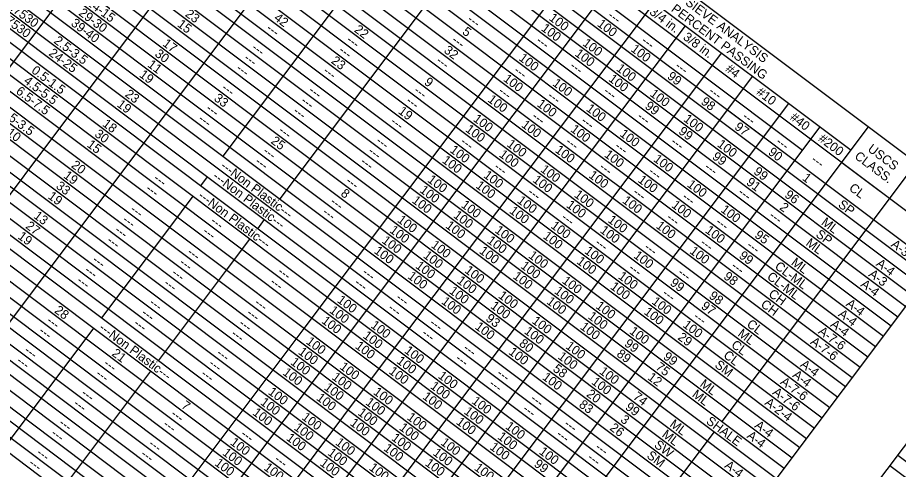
# Model space of a CAD drawing. Extents: x 627484.2 to 627517.5, y 367968.7 to 367996.9.
# Drawn here: x 627486.93 to 627492.24, y 367991.4 to 367994.12 of the extents above; entities that cross this region are included whole.
import ezdxf

# ---------------------------------------------------------------- set-up
doc = ezdxf.new("R2010")
doc.units = 0
doc.layers.add('Default', color=7, linetype='Continuous')

msp = doc.modelspace()

# ---------------------------------------------------------------- linework, layer by layer
at = {"layer": 'Default'}
for p, q in [((627487.4769, 367996.9012), (627492.7198, 367992.9642)), ((627487.3159, 367996.6868), (627492.5588, 367992.7498)), ((627487.2661, 367996.6205), (627491.6592, 367993.3217)), ((627487.2193, 367996.5581), (627491.4252, 367993.3998)), ((627487.1724, 367996.4958), (627492.4153, 367992.5588)), ((627487.1314, 367996.4412), (627492.3744, 367992.5042)), ((627487.0846, 367996.3788), (627492.3275, 367992.4419)), ((627487.0378, 367996.3164), (627492.2807, 367992.3795)), ((627486.9909, 367996.2541), (627492.2338, 367992.3171)), ((627486.95, 367996.1995), (627492.1929, 367992.2625)), ((627486.9031, 367996.1371), (627492.146, 367992.2002)), ((627486.7668, 367993.6668), (627488.5759, 367996.0759)), ((627486.8563, 367996.0747), (627492.0992, 367992.1378)), ((627486.8094, 367996.0124), (627492.0524, 367992.0754)), ((627486.7626, 367995.95), (627492.0055, 367992.013)), ((627486.7158, 367995.8876), (627491.9587, 367991.9507)), ((627486.6748, 367995.833), (627491.9177, 367991.8961)), ((627486.628, 367995.7707), (627491.8709, 367991.8337)), ((627487.1372, 367993.3887), (627488.9462, 367995.7978)), ((627486.5811, 367995.7083), (627491.824, 367991.7713)), ((627486.5343, 367995.6459), (627491.7772, 367991.709)), ((627486.4874, 367995.5836), (627491.7304, 367991.6466)), ((627486.4406, 367995.5212), (627491.6835, 367991.5842)), ((627487.5036, 367993.1135), (627489.3127, 367995.5227)), ((627486.3996, 367995.4666), (627491.6425, 367991.5297)), ((627486.3528, 367995.4042), (627491.5957, 367991.4673)), ((627486.306, 367995.3419), (627491.5489, 367991.4049)), ((627486.2591, 367995.2795), (627491.502, 367991.3425)), ((627486.2181, 367995.2249), (627491.461, 367991.288)), ((627486.1713, 367995.1625), (627491.4142, 367991.2256)), ((627486.1245, 367995.1002), (627491.3674, 367991.1632)), ((627486.0776, 367995.0378), (627491.3205, 367991.1008)), ((627486.0308, 367994.9754), (627491.2737, 367991.0385)), ((627485.9898, 367994.9208), (627491.2327, 367990.9839)), ((627485.943, 367994.8585), (627491.1859, 367990.9215)), ((627485.8961, 367994.7961), (627491.139, 367990.8591)), ((627485.8552, 367994.7415), (627491.0981, 367990.8046)), ((627485.8083, 367994.6791), (627491.0512, 367990.7422)), ((627488.6575, 367992.247), (627490.4666, 367994.6562)), ((627485.7615, 367994.6168), (627491.0044, 367990.6798)), ((627488.1687, 367993.2847), (627489.1698, 367994.6179)), ((627485.7146, 367994.5544), (627490.9576, 367990.6175)), ((627490.3612, 367994.5159), (627491.9517, 367993.3215)), ((627485.6678, 367994.492), (627490.9107, 367990.5551)), ((627485.621, 367994.4297), (627490.8639, 367990.4927)), ((627485.5741, 367994.3673), (627490.817, 367990.4303)), ((627488.5117, 367993.0271), (627489.5128, 367994.3603)), ((627488.8446, 367992.1065), (627490.5483, 367994.3753)), ((627485.5273, 367994.3049), (627490.7702, 367990.368)), ((627485.4805, 367994.2425), (627490.7234, 367990.3056)), ((627485.4395, 367994.188), (627490.6824, 367990.251)), ((627489.0629, 367991.9426), (627490.7666, 367994.2114)), ((627485.3926, 367994.1256), (627490.6356, 367990.1886)), ((627485.3458, 367994.0632), (627490.5887, 367990.1263)), ((627489.25, 367991.8021), (627490.9537, 367994.0709)), ((627485.299, 367994.0008), (627490.5419, 367990.0639)), ((627485.258, 367993.9463), (627490.5009, 367990.0093)), ((627485.2112, 367993.8839), (627490.4541, 367989.9469)), ((627489.4683, 367991.6382), (627491.172, 367993.907)), ((627485.1643, 367993.8215), (627490.4072, 367989.8846)), ((627485.1175, 367993.7592), (627490.3604, 367989.8222)), ((627489.6555, 367991.4977), (627491.3591, 367993.7665)), ((627485.0706, 367993.6968), (627490.3136, 367989.7598)), ((627485.0297, 367993.6422), (627490.2726, 367989.7053)), ((627489.8738, 367991.3337), (627491.5774, 367993.6025)), ((627484.9828, 367993.5798), (627490.2257, 367989.6429)), ((627491.2069, 367993.5638), (627492.4622, 367992.6212)), ((627484.936, 367993.5175), (627490.1789, 367989.5805)), ((627484.895, 367993.4629), (627490.1379, 367989.5259)), ((627490.0609, 367991.1932), (627491.7646, 367993.462)), ((627490.248, 367991.0527), (627492.0571, 367993.4619)), ((627484.8482, 367993.4005), (627490.0911, 367989.4636)), ((627485.6443, 367991.4005), (627487.1372, 367993.3887)), ((627484.8013, 367993.3381), (627490.0442, 367989.4012)), ((627484.7604, 367993.2836), (627490.0033, 367989.3466)), ((627491.1746, 367991.6859), (627492.3455, 367993.2452)), ((627491.8961, 367993.2475), (627492.5588, 367992.7498)), ((627484.7135, 367993.2212), (627489.9564, 367989.2842)), ((627484.6667, 367993.1588), (627489.9096, 367989.2219)), ((627488.034, 367993.1054), (627488.075, 367993.16)), ((627486.0107, 367991.1254), (627487.5036, 367993.1135)), ((627487.8467, 367992.8559), (627487.9872, 367993.043)), ((627490.9576, 367990.6175), (627492.7198, 367992.9642)), ((627487.4368, 367992.3102), (627487.8467, 367992.8559)), ((627488.3771, 367992.8478), (627488.418, 367992.9024)), ((627488.1897, 367992.5983), (627488.3302, 367992.7854)), ((627491.2374, 367990.1574), (627493.1196, 367992.664)), ((627487.7799, 367992.0526), (627488.1897, 367992.5983)), ((627486.3537, 367990.8678), (627487.39, 367992.2478)), ((627487.1646, 367990.2589), (627488.6575, 367992.247)), ((627487.3517, 367990.1184), (627488.8446, 367992.1065)), ((627486.6968, 367990.6102), (627487.7331, 367991.9902)), ((627487.57, 367989.9545), (627489.0629, 367991.9426)), ((627487.7571, 367989.814), (627489.25, 367991.8021)), ((627487.9754, 367989.65), (627489.4683, 367991.6382)), ((627490.5365, 367990.8361), (627491.1278, 367991.6236)), ((627488.1626, 367989.5095), (627489.6555, 367991.4977)), ((627492.2326, 367991.4828), (627497.4755, 367987.5459)), ((627492.1858, 367991.4204), (627497.4287, 367987.4835))]:
    msp.add_line(p, q, dxfattribs=at)

# ---------------------------------------------------------------- texts
for s, p in [('632315.7530', (627486.6876, 367994.3137)), ('632315.7530', (627486.6407, 367994.2514)), ('14-15', (627487.3419, 367994.2004)), ('SIEVE ANALYSIS', (627490.9485, 367994.2018)), ('3/4 in.', (627490.7323, 367994.1449)), ('PERCENT PASSING', (627490.8637, 367994.1623)), ('29-30', (627487.2941, 367994.1387)), ('23', (627487.9356, 367994.1325)), ('42', (627488.4705, 367994.1088)), ('100', (627490.1272, 367994.1085)), ('---', (627490.481, 367994.1233)), ('39-40', (627487.2472, 367994.0764)), ('15', (627487.8882, 367994.0705)), ('22', (627488.9541, 367994.0383)), ('---', (627489.6346, 367994.1004)), ('100', (627490.0803, 367994.0461)), ('100', (627490.4177, 367994.0732)), ('---', (627488.4237, 367994.0465)), ('5', (627489.6049, 367994.0252)), ('3/8 in.', (627490.935, 367993.9927)), ('2.5-3.5', (627487.1442, 367993.9709)), ('17', (627487.7997, 367993.9541)), ('---', (627488.9072, 367993.976)), ('---', (627489.541, 367993.9756)), ('---', (627490.0499, 367993.9714)), ('100', (627490.3299, 367993.9563)), ('---', (627490.6837, 367993.9711)), ('24-25', (627487.1136, 367993.8963)), ('30', (627487.7526, 367993.892)), ('---', (627488.3358, 367993.9295)), ('---', (627488.8604, 367993.9136)), ('32', (627489.4942, 367993.9132)), ('100', (627490.2831, 367993.8939)), ('100', (627490.6204, 367993.921)), ('11', (627487.7086, 367993.8275)), ('---', (627488.289, 367993.8671)), ('23', (627488.8149, 367993.8502)), ('---', (627489.4473, 367993.8509)), ('100', (627489.9457, 367993.8668)), ('0.5-1.5', (627487.0095, 367993.7915)), ('---', (627488.2422, 367993.8048)), ('---', (627488.7667, 367993.7889)), ('---', (627489.9153, 367993.7921)), ('---', (627490.2526, 367993.8192)), ('100', (627490.5326, 367993.8041)), ('---', (627490.8864, 367993.8188)), ('#4', (627491.19, 367993.8011)), ('4.5-5.5', (627486.9627, 367993.7292)), ('19', (627487.6592, 367993.767)), ('9', (627489.3758, 367993.7217)), ('100', (627489.852, 367993.742)), ('100', (627490.4858, 367993.7417)), ('99', (627490.8396, 367993.7564)), ('6.5-7.5', (627486.9158, 367993.6668)), ('---', (627488.1544, 367993.6878)), ('100', (627490.1484, 367993.7146)), ('23', (627487.5727, 367993.6491)), ('33', (627488.1089, 367993.6244)), ('---', (627488.6789, 367993.6719)), ('---', (627489.3126, 367993.6716)), ('100', (627489.7583, 367993.6173)), ('---', (627489.8216, 367993.6674)), ('---', (627490.118, 367993.6399)), ('---', (627490.4553, 367993.667)), ('100', (627490.7353, 367993.6518)), ('---', (627491.0891, 367993.6666)), ('#10', (627491.3763, 367993.6612)), ('19', (627487.5245, 367993.5877)), ('---', (627488.6321, 367993.6095)), ('---', (627489.2658, 367993.6092)), ('100', (627490.0547, 367993.5898)), ('100', (627490.3511, 367993.5624)), ('99', (627490.705, 367993.5771)), ('98', (627491.0428, 367993.6038)), ('2.5-3.5', (627486.8222, 367993.542)), ('---', (627488.0607, 367993.5631)), ('---', (627488.5852, 367993.5472)), ('19', (627489.219, 367993.5468)), ('#40', (627491.5791, 367993.509)), ('9-10', (627486.8068, 367993.456)), ('18', (627487.4372, 367993.4704)), ('---', (627488.0138, 367993.5007)), ('---', (627489.1721, 367993.4844)), ('100', (627489.6705, 367993.5004)), ('100', (627489.9611, 367993.4651)), ('---', (627490.0243, 367993.5151)), ('---', (627490.3207, 367993.4877)), ('---', (627490.658, 367993.5148)), ('100', (627490.938, 367993.4996)), ('97', (627491.2451, 367993.4519)), ('---', (627491.2918, 367993.5144)), ('30', (627487.3896, 367993.4086)), ('---', (627488.4974, 367993.4302)), ('100', (627489.6237, 367993.438)), ('100', (627490.2574, 367993.4376)), ('100', (627490.5538, 367993.4101)), ('99', (627490.9077, 367993.4249)), ('25', (627488.4514, 367993.3672)), ('---', (627489.0843, 367993.3675)), ('#200', (627491.7499, 367993.3807)), ('15', (627487.3438, 367993.3455)), ('100', (627489.53, 367993.3132)), ('---', (627489.5933, 367993.3633)), ('100', (627489.8732, 367993.3481)), ('100', (627490.1638, 367993.3129)), ('---', (627490.227, 367993.3629)), ('---', (627490.5234, 367993.3354)), ('---', (627490.8608, 367993.3626)), ('100', (627491.1407, 367993.3474)), ('90', (627491.4475, 367993.2999)), ('---', (627491.4945, 367993.3622)), ('USCS', (627492.0472, 367993.3188)), ('---', (627488.4037, 367993.3055)), ('---', (627489.0375, 367993.3051)), ('100', (627489.4832, 367993.2509)), ('100', (627489.8264, 367993.2858)), ('100', (627490.4602, 367993.2854)), ('100', (627490.7565, 367993.2579)), ('99', (627491.1104, 367993.2727)), ('CLASS.', (627491.968, 367993.2751)), ('20', (627487.2491, 367993.2214)), ('---Non Plastic---', (627488.1483, 367993.2168)), ('---', (627488.3569, 367993.2431)), ('---', (627488.9906, 367993.2427)), ('---', (627489.796, 367993.2111)), ('100', (627490.076, 367993.1959)), ('---', (627490.4297, 367993.2107)), ('---', (627491.0635, 367993.2103)), ('---', (627491.7065, 367993.2548)), ('19', (627487.2025, 367993.1589)), ('---Non Plastic---', (627488.1015, 367993.1545)), ('100', (627489.7327, 367993.161)), ('100', (627490.3665, 367993.1606)), ('---', (627490.7261, 367993.1832)), ('99', (627491.3599, 367993.1828)), ('1', (627491.6537, 367993.1451)), ('33', (627487.157, 367993.0955)), ('---', (627487.7445, 367993.1421)), ('---', (627488.9028, 367993.1258)), ('100', (627489.3954, 367993.1339)), ('100', (627489.6859, 367993.0986)), ('100', (627490.0291, 367993.1335)), ('100', (627490.6629, 367993.1332)), ('100', (627490.9592, 367993.1057)), ('91', (627491.3157, 367993.1185)), ('CL', (627491.9347, 367993.0835)), ('19', (627487.1088, 367993.0342)), ('---', (627487.6977, 367993.0797)), ('8', (627488.8728, 367993.0508)), ('100', (627489.3485, 367993.0715)), ('---', (627489.9987, 367993.0589)), ('100', (627490.2787, 367993.0437)), ('---', (627490.6324, 367993.0585)), ('---', (627491.2662, 367993.0581)), ('96', (627491.5469, 367993.0424)), ('---Non Plastic---', (627488.0136, 367993.0375)), ('---', (627488.8092, 367993.001)), ('100', (627489.3017, 367993.0092)), ('100', (627489.5981, 367992.9817)), ('100', (627489.9354, 367993.0088)), ('100', (627490.2318, 367992.9813)), ('100', (627490.5692, 367993.0084)), ('100', (627490.8656, 367992.981)), ('---', (627490.9288, 367993.031)), ('SP', (627491.8688, 367992.9836)), ('---', (627487.604, 367992.9549)), ('100', (627489.8886, 367992.9464)), ('100', (627491.162, 367992.9535)), ('2', (627491.5164, 367992.9678)), ('13', (627487.0223, 367992.9162)), ('---', (627487.5572, 367992.8926)), ('---', (627488.7623, 367992.9387)), ('100', (627489.2139, 367992.8922)), ('100', (627489.5512, 367992.9193)), ('---', (627490.2014, 367992.9066)), ('100', (627490.4814, 367992.8915)), ('---', (627490.8351, 367992.9063)), ('---', (627491.4533, 367992.9176)), ('ML', (627491.7679, 367992.8764)), ('27', (627486.9743, 367992.8548)), ('---', (627488.0876, 367992.8845)), ('100', (627489.167, 367992.8298)), ('100', (627489.5044, 367992.857)), ('100', (627489.8008, 367992.8295)), ('100', (627490.1382, 367992.8566)), ('100', (627490.4345, 367992.8291)), ('100', (627490.7719, 367992.8562)), ('100', (627491.0683, 367992.8287)), ('---', (627491.1315, 367992.8788)), ('19', (627486.9273, 367992.7925)), ('---', (627487.5104, 367992.8302)), ('---', (627488.0407, 367992.8221)), ('100', (627489.1202, 367992.7675)), ('100', (627489.754, 367992.7671)), ('100', (627490.0913, 367992.7942)), ('95', (627491.3663, 367992.8)), ('SP', (627491.7341, 367992.8043)), ('---', (627487.4635, 367992.7678)), ('100', (627489.4166, 367992.74)), ('---', (627490.4041, 367992.7544)), ('---', (627491.0379, 367992.754)), ('---', (627491.3186, 367992.7383)), ('ML', (627491.6743, 367992.7517)), ('A-3', (627492.1873, 367992.7444)), ('---', (627487.9471, 367992.6973)), ('100', (627489.0734, 367992.7051)), ('100', (627489.3698, 367992.6776)), ('100', (627489.7071, 367992.7047)), ('100', (627490.0035, 367992.6773)), ('100', (627490.3409, 367992.7044)), ('100', (627490.6373, 367992.6769)), ('---', (627490.7005, 367992.7269)), ('100', (627490.9746, 367992.704)), ('99', (627491.2719, 367992.6759)), ('---', (627487.3757, 367992.6509)), ('---', (627487.9002, 367992.635)), ('100', (627489.3229, 367992.6153)), ('100', (627489.9567, 367992.6149)), ('100', (627490.294, 367992.642)), ('CL-ML', (627491.4873, 367992.6116)), ('ML', (627491.5864, 367992.6347)), ('A-4', (627492.0979, 367992.6286)), ('---', (627487.3289, 367992.5885)), ('---', (627487.8534, 367992.5726)), ('---', (627488.493, 367992.58)), ('---', (627489.002, 367992.5758)), ('100', (627489.6193, 367992.5878)), ('---', (627490.6068, 367992.6022)), ('---', (627490.9032, 367992.5747)), ('98', (627491.1787, 367992.5508)), ('---', (627491.225, 367992.6135)), ('A-3', (627492.0527, 367992.5651)), ('---', (627487.282, 367992.5261)), ('---', (627488.4462, 367992.5177)), ('100', (627489.2761, 367992.5529)), ('100', (627489.5725, 367992.5254)), ('100', (627489.9098, 367992.5525)), ('100', (627490.2062, 367992.525)), ('100', (627490.5436, 367992.5521)), ('99', (627490.8564, 367992.5123)), ('CL-ML', (627491.4405, 367992.5493)), ('A-4', (627492.0042, 367992.5039)), ('---', (627487.8066, 367992.5102)), ('---', (627488.9551, 367992.5135)), ('100', (627489.5256, 367992.463)), ('100', (627490.1594, 367992.4627)), ('100', (627490.4967, 367992.4898)), ('100', (627488.8509, 367992.4088)), ('---', (627489.2047, 367992.4236)), ('100', (627489.4788, 367992.4007)), ('100', (627489.822, 367992.4356)), ('100', (627490.1125, 367992.4003)), ('100', (627490.7463, 367992.3999)), ('---', (627490.8095, 367992.45)), ('98', (627491.0909, 367992.4338)), ('CH', (627491.4495, 367992.4449)), ('28', (627487.1479, 367992.3464)), ('---', (627487.7187, 367992.3933)), ('---', (627488.3525, 367992.3929)), ('100', (627488.8041, 367992.3465)), ('---', (627489.1578, 367992.3612)), ('100', (627489.7752, 367992.3732)), ('100', (627490.4089, 367992.3728)), ('97', (627491.0436, 367992.3717)), ('CH', (627491.4027, 367992.3826)), ('A-4', (627491.9164, 367992.387)), ('---', (627487.6719, 367992.3309)), ('---', (627488.3057, 367992.3305)), ('93', (627489.7461, 367992.2975)), ('100', (627490.3621, 367992.3105)), ('100', (627490.6995, 367992.3376)), ('---', (627490.9966, 367992.3095)), ('A-4', (627491.8696, 367992.3246)), ('---', (627487.1005, 367992.2844)), ('---', (627487.6251, 367992.2685)), ('---', (627488.2588, 367992.2682)), ('100', (627488.7572, 367992.2841)), ('100', (627489.0536, 367992.2566)), ('---', (627489.4074, 367992.2714)), ('100', (627489.6815, 367992.2484)), ('100', (627490.0247, 367992.2833)), ('100', (627490.3153, 367992.2481)), ('100', (627490.9334, 367992.2594)), ('CL', (627491.3185, 367992.2629)), ('A-4', (627491.8227, 367992.2622)), ('---', (627487.0537, 367992.2221)), ('---Non Plastic---', (627487.4165, 367992.2423)), ('---', (627488.212, 367992.2058)), ('100', (627489.0068, 367992.1942)), ('---', (627489.3605, 367992.209)), ('100', (627489.9779, 367992.221)), ('100', (627490.6116, 367992.2206)), ('29', (627490.903, 367992.1847)), ('ML', (627491.2644, 367992.2059)), ('A-7-6', (627491.749, 367992.2201)), ('100', (627488.6635, 367992.1593)), ('100', (627488.9599, 367992.1319)), ('80', (627489.9473, 367992.1464)), ('100', (627490.2274, 367992.1311)), ('99', (627490.5813, 367992.1459)), ('CL', (627491.2248, 367992.1381)), ('A-7-6', (627491.7021, 367992.1577)), ('---', (627486.9659, 367992.1051)), ('21', (627487.4931, 367992.0872)), ('100', (627488.6167, 367992.097)), ('100', (627489.2563, 367992.1044)), ('---', (627489.6101, 367992.1192)), ('100', (627489.8842, 367992.0962)), ('89', (627490.5344, 367992.0835)), ('CL', (627491.178, 367992.0758)), ('---', (627486.919, 367992.0427)), ('---', (627488.1242, 367992.0888)), ('100', (627488.5699, 367992.0346)), ('100', (627489.2095, 367992.042)), ('---', (627489.5633, 367992.0568)), ('100', (627490.1806, 367992.0688)), ('99', (627490.8152, 367992.0677)), ('---', (627487.4436, 367992.0268)), ('---', (627488.0773, 367992.0265)), ('100', (627488.523, 367991.9722)), ('100', (627488.8663, 367992.0071)), ('100', (627489.1626, 367991.9796)), ('58', (627490.1507, 367991.9937)), ('100', (627490.4301, 367991.9789)), ('75', (627490.7691, 367992.0048)), ('SM', (627491.1257, 367992.0175)), ('A-4', (627491.6413, 367992.0205)), ('---', (627487.3967, 367991.9645)), ('---', (627488.0305, 367991.9641)), ('100', (627488.8194, 367991.9447)), ('100', (627489.459, 367991.9522)), ('---', (627489.8128, 367991.967)), ('100', (627490.0869, 367991.944)), ('100', (627490.3833, 367991.9165)), ('12', (627490.7215, 367991.943)), ('A-4', (627491.5944, 367991.9581)), ('100', (627488.7726, 367991.8824)), ('100', (627489.4122, 367991.8898)), ('---', (627489.766, 367991.9046)), ('ML', (627491.0361, 367991.9019)), ('A-7-6', (627491.5206, 367991.916)), ('---', (627487.3089, 367991.8475)), ('100', (627488.4352, 367991.8553)), ('100', (627488.7258, 367991.82)), ('100', (627489.069, 367991.8549)), ('100', (627489.3654, 367991.8274)), ('20', (627490.3527, 367991.842)), ('74', (627490.6335, 367991.8262)), ('ML', (627490.9893, 367991.8395)), ('A-7-6', (627491.4738, 367991.8536)), ('---', (627487.2621, 367991.7851)), ('7', (627487.9122, 367991.7725)), ('100', (627488.3884, 367991.7929)), ('100', (627489.0221, 367991.7925)), ('100', (627489.6617, 367991.8)), ('---', (627490.0155, 367991.8147)), ('83', (627490.3074, 367991.7784)), ('99', (627490.5869, 367991.7637)), ('A-2-4', (627491.4268, 367991.7913)), ('---', (627487.849, 367991.7224)), ('100', (627488.3415, 367991.7305)), ('100', (627488.9753, 367991.7302)), ('100', (627489.6149, 367991.7376)), ('---', (627489.9687, 367991.7524)), ('---', (627487.1743, 367991.6682)), ('100', (627488.6379, 367991.7031)), ('100', (627488.9285, 367991.6678)), ('100', (627489.2717, 367991.7027)), ('100', (627489.5681, 367991.6752)), ('3', (627490.5576, 367991.6881)), ('ML', (627490.8546, 367991.6602)), ('SHALE', (627491.0737, 367991.6786)), ('A-4', (627491.3661, 367991.6541)), ('---', (627487.8022, 367991.66)), ('100', (627488.5911, 367991.6407)), ('100', (627489.2248, 367991.6403)), ('100', (627489.8645, 367991.6477)), ('---', (627490.2182, 367991.6625)), ('26', (627490.4931, 367991.639)), ('ML', (627490.8078, 367991.5978)), ('---', (627487.1274, 367991.6058)), ('100', (627488.2069, 367991.5512)), ('---', (627488.2701, 367991.6013)), ('100', (627488.5443, 367991.5783)), ('100', (627488.8406, 367991.5508)), ('100', (627489.178, 367991.5779)), ('100', (627489.4744, 367991.5505)), ('100', (627489.8176, 367991.5854)), ('---', (627490.1714, 367991.6002)), ('A-4', (627491.3193, 367991.5917)), ('---', (627487.7144, 367991.5431)), ('100', (627489.1312, 367991.5156)), ('100', (627489.7708, 367991.523)), ('100', (627490.0672, 367991.4955)), ('---', (627490.4053, 367991.522)), ('SW', (627490.7605, 367991.5358)), ('---', (627487.0396, 367991.4889)), ('---', (627487.6675, 367991.4807)), ('100', (627488.1601, 367991.4888)), ('100', (627488.7938, 367991.4885)), ('100', (627489.4276, 367991.4881)), ('---', (627490.3585, 367991.4596)), ('SM', (627490.7159, 367991.4717)), ('---', (627486.9928, 367991.4265)), ('100', (627488.1132, 367991.4265)), ('100', (627488.4096, 367991.399)), ('---', (627488.4728, 367991.449)), ('100', (627488.747, 367991.4261)), ('100', (627489.0434, 367991.3986)), ('100', (627489.3807, 367991.4257)), ('100', (627489.6771, 367991.3983)), ('99', (627490.0368, 367991.4208)), ('A-4', (627491.1846, 367991.4124))]:
    msp.add_text(s, height=0.055, rotation=323.0968, dxfattribs=at).set_placement(p)

doc.saveas('drawing.dxf')
